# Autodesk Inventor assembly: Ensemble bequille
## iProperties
Shininess: 64.0
Length Units: 11269
Angle Units: 11279
Time Units: 11290
Mass Units: 11283
Length Display Precision: 3
Angle Display Precision: 2
Compacted: True
Created: 2006-01
Part Number: Ensemble bequille
Document SubType Name: Assembly
Designer: Fricot
Density: 0.0
Volumn: 0.0
Area: 0.0
PropertySet Name: Model Information
Control State: 0
Master: False
Checked Out: False
Norme de conversion: STEP AP203
Nom du fichier: Ensemble bequille.STEP
Préprocesseur: SolidWorks 2003099
Postprocesseur: Build: 120c, Release: 6 SP2 - Date: Mon 01/13/2003
Unités envoyées: MILLIMETERS
Incertitude: 0.0
Author: Fricot
